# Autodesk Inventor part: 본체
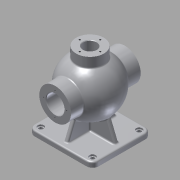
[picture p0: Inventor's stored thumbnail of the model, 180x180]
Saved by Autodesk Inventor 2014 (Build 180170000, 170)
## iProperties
Created: 2015-10
Part Number: 본체
Material: Aluminum 6061
Document SubType Name: Modeling
Designer: youjin15
Density: 2.71 g/cm^3
Appearance: Aluminum - Flat
Mass: 1509.6 g
Surface Area: 1153.65 cm^2
Volume: 557.048 cm^3
Author: youjin15
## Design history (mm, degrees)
sketch "Sketch1"
  geometry: L1 (45.5, -62.5)-(-45.5, -62.5); L2 (-57.5, -50.5)-(-57.5, 50.5); L3 (-45.5, 62.5)-(45.5, 62.5); L4 (57.5, 50.5)-(57.5, -50.5); L5 (57.5, -62.5)-(-57.5, 62.5); L6 (-57.5, -62.5)-(57.5, 62.5); A1 r 12 centre (-45.5, 50.5) between (-45.5, 62.5) and (-57.5, 50.5); A2 r 12 centre (45.5, 50.5) between (57.5, 50.5) and (45.5, 62.5); A3 r 12 centre (45.5, -50.5) between (45.5, -62.5) and (57.5, -50.5); A4 r 12 centre (-45.5, -50.5) between (-57.5, -50.5) and (-45.5, -62.5); 1 further point
  constraints: 12 end point, 8 point on circle, 8 point on line, 8 tangent, 4 centre point, 3 equal radius, 2 midpoint, 2 parallel, 1 horizontal, 1 perpendicular
  dimensions: "d0" = 115 distance of L5.end L6.end; "d1" = 125 distance of L6.start L5.end; "d2" = 12 radius of A1
extrude "Extrusion1" new body sketch "Sketch1" distance "d3" = 10; taper "d4" = 0 deg
sketch "Sketch2"
  geometry: L1 (53, 85)-(-53, 85); L2 (45.5, 0)-(-45.5, 0) reference; A1 r 53 centre (0, 85) between (53, 85) and (-53, 85); 4 further points
  constraints: 2 end point, 2 midpoint, 2 point on circle, 2 vertical alignment, 1 centre point, 1 horizontal
  dimensions: "d5" = 106 distance of L1.start L1.end; "d6" = 53 radius of A1; "d7" = 85 distance between parallel lines of L2 L1; "d9" = 43 distance of A1.centre point (0, 128)
revolve "Revolution1" sketch "Sketch2" stored, may be unused: angle "d10" = 90 deg
sketch "Sketch3"
  geometry: L1 (68, 85)-(-68, 85); L2 (-45.5, 0)-(45.5, 0) reference; L3 (68, 85)-(68, 116); L4 (68, 116)-(42.988, 116); L5 (-68, 85)-(-68, 116); L6 (-68, 116)-(-42.988, 116); A1 r 53 centre (0, 85) between (42.988, 116) and (-42.988, 116) reference; A2 r 53 centre (0, 85) between (-42.988, 116) and (-53, 85); A3 r 53 centre (0, 85) between (53, 85) and (42.988, 116); 2 further points
  constraints: 10 end point, 8 point on circle, 4 perpendicular, 2 centre point, 2 coincident, 2 concentric, 1 collinear, 1 horizontal, 1 midpoint, 1 point on line, 1 vertical alignment
  dimensions: "d11" = 136 distance of L1.start L1.end; "d12" = 85 distance between parallel lines of L2 L1; "d13" = 62 diameter of L4 L1
revolve "Revolution2" sketch "Sketch3" stored, may be unused: angle "d14" = 90 deg
hole "Hole1" diameter "d17" = 35; stored, may be unused: countersink angle "d21" = 90 deg, drill point angle "d23" = 0 deg; dims "d15" = 10, "d16" = 10, "d18" = 6, "d19" = 4, "d20" = 2, "d22" = 8
sketch "Sketch4"
  geometry: L1 (-43, 85)-(43, 85); L2 (45.5, 0)-(-45.5, 0) reference; A1 r 53 centre (0, 85) between (42.988, 116) and (42.988, 54) reference; A2 r 43 centre (0, 85) between (43, 85) and (-43, 85); 2 further points
  constraints: 2 end point, 2 point on circle, 1 centre point, 1 coincident, 1 horizontal, 1 midpoint, 1 vertical alignment
  dimensions: "d24" = 43 radius of A2; "d25" = 85 distance between parallel lines of L2 L1
revolve "Revolution3" sketch "Sketch4" stored, may be unused: angle "d26" = 90 deg
sketch "Sketch5"
  geometry: L1 (42.988, 116)-(42.988, 54) reference; L2 (68, 54)-(68, 116) reference; L3 (39.278, 102.5)-(68, 102.5) reference; L4 (39.278, 67.5)-(68, 67.5) reference; L5 (42.988, 116)-(68, 116) reference; L6 (68, 116)-(68, 102.5) reference; L7 (68, 102.5)-(39.278, 102.5) reference; L8 (-39.278, 102.5)-(-68, 102.5) reference; L9 (-68, 102.5)-(-68, 116) reference; L10 (-68, 116)-(-42.988, 116) reference; L11 (68, 54)-(42.988, 54) reference; L12 (-42.988, 54)-(-68, 54) reference; L13 (-68, 54)-(-68, 67.5) reference; L14 (-68, 67.5)-(-39.278, 67.5) reference; L15 (39.278, 67.5)-(68, 67.5) reference; L16 (68, 67.5)-(68, 54) reference; L17 (57.5, 10)-(57.5, 0) reference; L18 (57.5, 0)-(-57.5, 0) reference; L19 (-57.5, 0)-(-57.5, 10) reference; L20 (-57.5, 10)-(57.5, 10) reference; L21 (0, 85)-(68, 85); L22 (52, 85)-(52, 103.5); L23 (52, 103.5)-(50.25, 103.5); L24 (50.25, 103.5)-(50.25, 85); A1 r 43 centre (0, 85) between (39.278, 102.5) and (-39.278, 102.5) reference; A2 r 53 centre (0, 85) between (42.988, 116) and (-42.988, 116) reference; A3 r 53 centre (0, 85) between (-42.988, 54) and (42.988, 54) reference; A4 r 43 centre (0, 85) between (-39.278, 67.5) and (39.278, 67.5) reference; 1 further point
  constraints: 8 end point, 3 perpendicular, 2 point on line, 1 midpoint
  dimensions: "d27" = 1.75 distance of L22.end L23.end; "d28" = 16 distance between parallel lines of L2 L22; "d29" = 37 diameter of L23 L21
revolve "Revolution4" sketch "Sketch5" stored, may be unused: angle "d30" = 90 deg
workplane "Work Plane1"
sketch "Sketch6"
  geometry: C1 r 27 at (0, 0); 1 further point
  constraints: 1 centre point, 1 coincident
  dimensions: "d33" = 54 diameter of C1
extrude "Extrusion2" join sketch "Sketch6" stored distance "d34" = 10; taper "d35" = 0 deg
hole "Hole2" diameter "d38" = 26; stored, may be unused: countersink angle "d42" = 90 deg, drill point angle "d44" = 0 deg; dims "d36" = 10, "d37" = 10, "d39" = 6, "d40" = 4, "d41" = 2, "d43" = 8
sketch "Sketch11"
  geometry: L1 (-27, 130.607)-(-27, 150) reference; L2 (-27, 150)-(-13, 150) reference; L3 (-13, 150)-(-13, 125.988) reference; L4 (-39.278, 102.5)-(-68, 102.5) reference; L5 (-68, 102.5)-(-68, 116) reference; L6 (-68, 116)-(-42.988, 116) reference; L7 (52, 103.5)-(50.25, 103.5) reference; L8 (50.25, 103.5)-(50.25, 102.5) reference; L9 (50.25, 102.5)-(39.278, 102.5) reference; L10 (13, 125.988)-(13, 150) reference; L11 (13, 150)-(27, 150) reference; L12 (27, 150)-(27, 130.607) reference; L13 (42.988, 116)-(68, 116) reference; L14 (68, 116)-(68, 102.5) reference; L15 (68, 102.5)-(52, 102.5) reference; L16 (52, 102.5)-(52, 103.5) reference; L17 (50.25, 66.5)-(52, 66.5) reference; L18 (52, 66.5)-(52, 67.5) reference; L19 (52, 67.5)-(68, 67.5) reference; L20 (68, 67.5)-(68, 54) reference; L21 (68, 54)-(42.988, 54) reference; L22 (-42.988, 54)-(-68, 54) reference; L23 (-68, 54)-(-68, 67.5) reference; L24 (-68, 67.5)-(-39.278, 67.5) reference; L25 (39.278, 67.5)-(50.25, 67.5) reference; L26 (50.25, 67.5)-(50.25, 66.5) reference; L27 (57.5, 10)-(57.5, 0) reference; L28 (57.5, 0)-(-57.5, 0) reference; L29 (-57.5, 0)-(-57.5, 10) reference; L30 (-57.5, 10)-(57.5, 10) reference; L31 (-47.5, 10)-(-29.744, 53.947); L32 (29.744, 53.947)-(47.5, 10); L33 (-47.5, 10)-(47.5, 10); A1 r 53 centre (0, 85) between (-27, 130.607) and (-42.988, 116) reference; A2 r 43 centre (0, 85) between (-13, 125.988) and (-39.278, 102.5) reference; A3 r 43 centre (0, 85) between (39.278, 102.5) and (13, 125.988) reference; A4 r 53 centre (0, 85) between (42.988, 116) and (27, 130.607) reference; A5 r 53 centre (0, 85) between (-42.988, 54) and (42.988, 54) reference; A6 r 43 centre (0, 85) between (-39.278, 67.5) and (39.278, 67.5) reference; 1 further point
  constraints: 6 end point, 2 point on circle, 2 point on line
  dimensions: "d61" = 10 distance of L29.end L31.start; "d62" = 10 distance of L27.start L32.end; "d63" = 22 deg angle of L27 L32; "d64" = 22 deg angle of L29 L31
extrude "Extrusion5" join sketch "Sketch11" stored distance "d65" = 8; taper "d66" = 0 deg
sketch "Sketch12"
  geometry: L1 (-13, 150)-(-13, 125.988) reference; L2 (13, 125.988)-(13, 150) reference; L3 (13, 150)-(27, 150) reference; L4 (27, 150)-(27, 130.607) reference; L5 (4, 32.151)-(4, 10) reference; L6 (4, 10)-(62.5, 10) reference; L7 (62.5, 10)-(62.5, 0) reference; L8 (62.5, 0)-(-62.5, 0) reference; L9 (-62.5, 0)-(-62.5, 10) reference; L10 (-62.5, 10)-(-4, 10) reference; L11 (-4, 10)-(-4, 32.151) reference; L12 (-27, 130.607)-(-27, 150) reference; L13 (-27, 150)-(-13, 150) reference; L14 (-52.5, 10)-(-33.226, 57.705); L15 (33.226, 57.705)-(52.5, 10); A1 r 43 centre (0, 85) between (-13, 125.988) and (13, 125.988) reference; A2 r 53 centre (0, 85) between (4, 32.151) and (27, 130.607) reference; A3 r 53 centre (0, 85) between (-27, 130.607) and (-4, 32.151) reference; 1 further point
  constraints: 4 end point, 2 point on circle, 2 point on line
  dimensions: "d67" = 10 distance of L6.end L15.end; "d68" = 22 deg angle of L7 L15; "d69" = 10 distance of L9.end L14.start; "d70" = 22 deg angle of L9 L14
extrude "Extrusion6" join sketch "Sketch12" stored distance "d71" = 8; taper "d72" = 0 deg
sketch "Sketch13"
  geometry: A1 r 12 centre (45.5, 50.5) between (57.5, 50.5) and (45.5, 62.5) reference; 5 further points
  constraints: 2 horizontal alignment, 2 vertical alignment, 1 coincident
  dimensions: "d73" = 91 distance of point (45.5, 50.5) point (-45.5, 50.5); "d74" = 101 distance of point (45.5, -50.5) point (45.5, 50.5)
hole "Hole3" sketch "Sketch13" at (-45.5, 50.5), (45.5, 50.5), (-45.5, -50.5), (45.5, -50.5) diameter "d75" = 8; stored, may be unused: countersink angle "d79" = 90 deg, drill point angle "d81" = 0 deg; dims "d76" = 6, "d77" = 12, "d78" = 3, "d80" = 8
sketch "Sketch14" dims "d82" = 45
  geometry: C1 r 31 at (0, 0) reference; 3 further points
  constraints: 2 vertical alignment, 1 coincident, 2 other
hole "Hole4" sketch "Sketch14" at (0, 22.5) diameter "d83" = 3.242; stored, may be unused: countersink angle "d87" = 90 deg, drill point angle "d89" = 118 deg; dims "d84" = 12, "d85" = 12, "d86" = 3, "d88" = 15
pattern_circular "Circular Pattern1" dims angle "d91" = 360 deg
sketch "Sketch15" dims "d93" = 48
  geometry: C1 r 31 at (0, 0) reference; 3 further points
  constraints: 2 vertical alignment, 1 coincident, 2 other
hole "Hole5" sketch "Sketch15" at (0, 24) diameter "d94" = 3.242; stored, may be unused: countersink angle "d98" = 90 deg, drill point angle "d100" = 118 deg; dims "d95" = 16, "d96" = 4, "d97" = 2, "d99" = 19
pattern_circular "Circular Pattern2" dims angle "d102" = 360 deg
sketch "Sketch16" dims "d104" = 40
  geometry: C1 r 27 at (0, 0) reference; 2 further points
  constraints: 2 vertical alignment, 1 coincident, 2 other
hole "Hole6" sketch "Sketch16" at (0, 20) diameter "d105" = 3.242; stored, may be unused: countersink angle "d109" = 90 deg, drill point angle "d111" = 118 deg; dims "d106" = 9, "d107" = 4, "d108" = 2, "d110" = 11
pattern_circular "Circular Pattern3" dims angle "d113" = 360 deg
workplane "Work Plane2"
sketch "Sketch17"
  geometry: L1 (68, 100.232)-(68, 69.768) reference; L2 (68, 69.768)-(42.988, 69.768) reference; L3 (4, 39.569)-(4, 10) reference; L4 (4, 10)-(57.5, 10) reference; L5 (57.5, 10)-(57.5, 0) reference; L6 (57.5, 0)-(-57.5, 0) reference; L7 (-57.5, 0)-(-57.5, 10) reference; L8 (-57.5, 10)-(-4, 10) reference; L9 (-4, 10)-(-4, 39.569) reference; L10 (-42.988, 69.768)-(-68, 69.768) reference; L11 (-68, 69.768)-(-68, 100.232) reference; L12 (-68, 100.232)-(-42.988, 100.232) reference; L13 (42.988, 100.232)-(68, 100.232) reference; L14 (0, 150)-(0, 130.607) reference; C1 r 33.466 at (0, 85) reference; A1 r 45.607 centre (0, 85) between (4, 39.569) and (42.988, 69.768) reference; A2 r 45.607 centre (0, 85) between (-42.988, 69.768) and (-4, 39.569) reference; A3 r 45.607 centre (0, 85) between (0, 130.607) and (-42.988, 100.232) reference; A4 r 45.607 centre (0, 85) between (42.988, 100.232) and (0, 130.607) reference; 2 further points
  constraints: 1 vertical alignment, 1 other
  dimensions: "d116" = 10 distance of point (0, 140) L14.start
emboss "Emboss1" sketch "Sketch17" dims "d0" = 115, "d1" = 125, "d2" = 12, "d117" = 0.5, "d118" = 0
fillet "Fillet1" dims "d119" = 3
chamfer "Chamfer1" distance "d120" = 1; stored, may be unused: second distance "d121" = 2, angle "d122" = 45 deg
body "Solid1"
node "Projected Loop1"
node "Project Cut Edges1"
node "Project Cut Edges4"
node "Project Cut Edges5"
node "Project Cut Edges6"
other parameters: "d115" = -27
